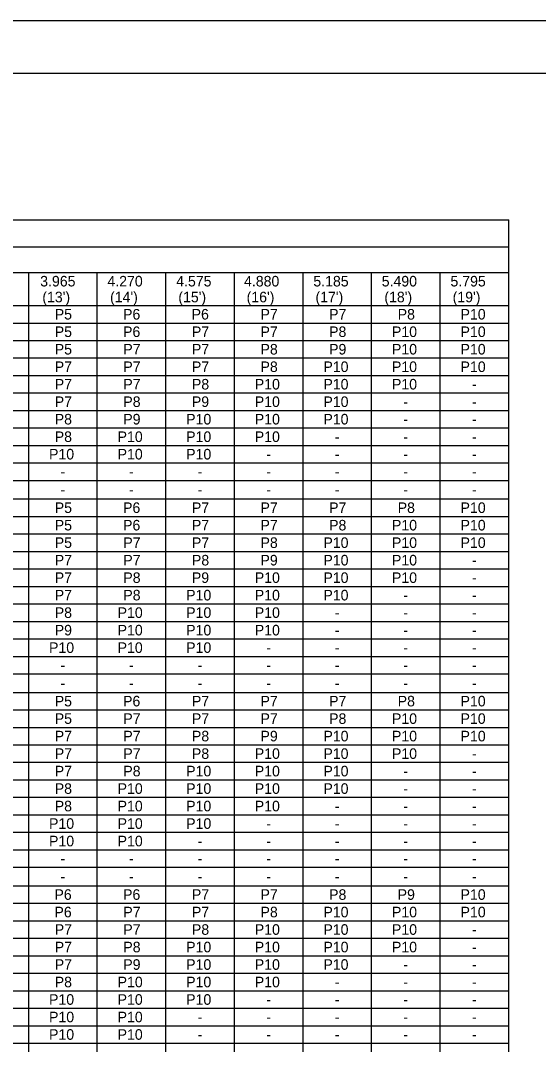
# Model space of a CAD drawing. Extents: x 637580 to 641008, y 294594 to 295782.
# Drawn here: x 639574.7 to 639722, y 295490.5 to 295781.6 of the extents above; entities that cross this region are included whole.
import ezdxf

# ---------------------------------------------------------------- set-up
doc = ezdxf.new("R2010")
doc.units = 0
for name, color, linetype in [('1', 7, 'Continuous'), ('2', 7, 'Continuous'), ('PLT-BNDY', 7, 'Continuous')]:
    doc.layers.add(name, color=color, linetype=linetype)

msp = doc.modelspace()

# ---------------------------------------------------------------- linework, layer by layer
at = {"layer": '1'}
for p, q in [((639302.31, 295766.63), (640088.31, 295766.63)), ((639346.67, 295724.98), (639713.6, 295724.98)), ((639713.6, 295260.68), (639713.6, 295724.98)), ((639346.67, 295717.3), (639713.6, 295717.3)), ((639346.67, 295700.6), (639713.6, 295700.6)), ((639346.67, 295645.61), (639713.6, 295645.61)), ((639346.67, 295590.62), (639713.6, 295590.62)), ((639346.67, 295535.63), (639713.6, 295535.63))]:
    msp.add_line(p, q, dxfattribs=at)
at = {"layer": '2'}
for p, q in [((639401.48, 295709.96), (639713.6, 295709.96)), ((639577.04, 295260.68), (639577.04, 295709.96)), ((639596.55, 295260.68), (639596.55, 295709.96)), ((639616.06, 295260.68), (639616.06, 295709.96)), ((639635.57, 295260.68), (639635.57, 295709.96)), ((639655.07, 295260.68), (639655.07, 295709.96)), ((639674.58, 295260.68), (639674.58, 295709.96)), ((639694.09, 295260.68), (639694.09, 295709.96)), ((639373.47, 295695.62), (639713.6, 295695.62)), ((639373.47, 295690.65), (639713.6, 295690.65)), ((639373.47, 295685.68), (639713.6, 295685.68)), ((639373.47, 295680.71), (639713.6, 295680.71)), ((639373.47, 295675.73), (639713.6, 295675.73)), ((639373.47, 295670.76), (639713.6, 295670.76)), ((639373.47, 295665.79), (639713.6, 295665.79)), ((639373.47, 295660.82), (639713.6, 295660.82)), ((639373.47, 295655.84), (639713.6, 295655.84)), ((639373.47, 295650.87), (639713.6, 295650.87)), ((639373.47, 295640.63), (639713.6, 295640.63)), ((639373.47, 295635.66), (639713.6, 295635.66)), ((639373.47, 295630.69), (639713.6, 295630.69)), ((639373.47, 295625.72), (639713.6, 295625.72)), ((639373.47, 295620.74), (639713.6, 295620.74)), ((639373.47, 295615.77), (639713.6, 295615.77)), ((639373.47, 295610.8), (639713.6, 295610.8)), ((639373.47, 295605.83), (639713.6, 295605.83)), ((639373.47, 295600.85), (639713.6, 295600.85)), ((639373.47, 295595.88), (639713.6, 295595.88)), ((639373.47, 295585.64), (639713.6, 295585.64)), ((639373.47, 295580.67), (639713.6, 295580.67)), ((639373.47, 295575.7), (639713.6, 295575.7)), ((639373.47, 295570.73), (639713.6, 295570.73)), ((639373.47, 295565.75), (639713.6, 295565.75)), ((639373.47, 295560.78), (639713.6, 295560.78)), ((639373.47, 295555.81), (639713.6, 295555.81)), ((639373.47, 295550.84), (639713.6, 295550.84)), ((639373.47, 295545.86), (639713.6, 295545.86)), ((639373.47, 295540.89), (639713.6, 295540.89)), ((639373.47, 295530.65), (639713.6, 295530.65)), ((639373.47, 295525.68), (639713.6, 295525.68)), ((639373.47, 295520.71), (639713.6, 295520.71)), ((639373.47, 295515.74), (639713.6, 295515.74)), ((639373.47, 295510.76), (639713.6, 295510.76)), ((639373.47, 295505.79), (639713.6, 295505.79)), ((639373.47, 295500.82), (639713.6, 295500.82)), ((639373.47, 295495.85), (639713.6, 295495.85)), ((639373.47, 295490.87), (639713.6, 295490.87))]:
    msp.add_line(p, q, dxfattribs=at)
at = {"layer": 'PLT-BNDY'}
msp.add_lwpolyline([(639262.31, 295781.63), (640103.31, 295781.63), (640103.31, 295187.63), (639262.31, 295187.63)], close=True, dxfattribs=at)

# ---------------------------------------------------------------- texts
at = {"layer": '1'}
for s, p in [('3.965', (639580.31, 295706.01)), ('4.270', (639599.43, 295706.01)), ('4.575', (639618.99, 295706.01)), ('4.880', (639638.28, 295706.01)), ('5.185', (639657.99, 295706.01)), ('5.490', (639677.44, 295706.01)), ('5.795', (639696.99, 295706.01)), ("(13')", (639580.92, 295701.51)), ("(14')", (639600.18, 295701.51)), ("(15')", (639619.6, 295701.51)), ("(16')", (639639.02, 295701.51)), ("(17')", (639658.6, 295701.51)), ("(18')", (639678.19, 295701.51)), ("(19')", (639697.61, 295701.51)), ('P5', (639584.45, 295696.61)), ('P6', (639603.87, 295696.61)), ('P6', (639623.38, 295696.61)), ('P7', (639642.97, 295696.61)), ('P7', (639662.48, 295696.61)), ('P8', (639681.98, 295696.61)), ('P10', (639699.86, 295696.61)), ('P5', (639584.45, 295691.64)), ('P6', (639603.87, 295691.64)), ('P7', (639623.46, 295691.64)), ('P7', (639642.97, 295691.64)), ('P8', (639662.48, 295691.64)), ('P10', (639680.35, 295691.64)), ('P10', (639699.86, 295691.64)), ('P5', (639584.45, 295686.67)), ('P7', (639603.95, 295686.67)), ('P7', (639623.46, 295686.67)), ('P8', (639642.97, 295686.67)), ('P9', (639662.47, 295686.67)), ('P10', (639680.35, 295686.67)), ('P10', (639699.86, 295686.67)), ('P7', (639584.45, 295681.69)), ('P7', (639603.95, 295681.69)), ('P7', (639623.46, 295681.69)), ('P8', (639642.97, 295681.69)), ('P10', (639660.85, 295681.69)), ('P10', (639680.35, 295681.69)), ('P10', (639699.86, 295681.69)), ('P7', (639584.45, 295676.72)), ('P7', (639603.95, 295676.72)), ('P8', (639623.46, 295676.72)), ('P10', (639641.34, 295676.72)), ('P10', (639660.85, 295676.72)), ('P10', (639680.35, 295676.72)), ('-', (639703.11, 295676.72)), ('P7', (639584.45, 295671.75)), ('P8', (639603.95, 295671.75)), ('P9', (639623.45, 295671.75)), ('P10', (639641.34, 295671.75)), ('P10', (639660.85, 295671.75)), ('-', (639683.6, 295671.75)), ('-', (639703.11, 295671.75)), ('P8', (639584.45, 295666.78)), ('P9', (639603.94, 295666.78)), ('P10', (639621.83, 295666.78)), ('P10', (639641.34, 295666.78)), ('P10', (639660.85, 295666.78)), ('-', (639683.6, 295666.78)), ('-', (639703.11, 295666.78)), ('P8', (639584.45, 295661.8)), ('P10', (639602.33, 295661.8)), ('P10', (639621.83, 295661.8)), ('P10', (639641.34, 295661.8)), ('-', (639664.1, 295661.8)), ('-', (639683.6, 295661.8)), ('-', (639703.11, 295661.8)), ('P10', (639582.82, 295656.83)), ('P10', (639602.33, 295656.83)), ('P10', (639621.83, 295656.83)), ('-', (639644.59, 295656.83)), ('-', (639664.1, 295656.83)), ('-', (639683.6, 295656.83)), ('-', (639703.11, 295656.83)), ('-', (639586.07, 295651.86)), ('-', (639605.57, 295651.86)), ('-', (639625.08, 295651.86)), ('-', (639644.59, 295651.86)), ('-', (639664.1, 295651.86)), ('-', (639683.6, 295651.86)), ('-', (639703.11, 295651.86)), ('-', (639586.07, 295646.74)), ('-', (639605.57, 295646.74)), ('-', (639625.08, 295646.74)), ('-', (639644.59, 295646.74)), ('-', (639664.1, 295646.74)), ('-', (639683.6, 295646.74)), ('-', (639703.11, 295646.74)), ('P5', (639584.45, 295641.62)), ('P6', (639603.87, 295641.62)), ('P7', (639623.46, 295641.62)), ('P7', (639642.97, 295641.62)), ('P7', (639662.48, 295641.62)), ('P8', (639681.98, 295641.62)), ('P10', (639699.86, 295641.62)), ('P5', (639584.45, 295636.65)), ('P6', (639603.87, 295636.65)), ('P7', (639623.46, 295636.65)), ('P7', (639642.97, 295636.65)), ('P8', (639662.48, 295636.65)), ('P10', (639680.35, 295636.65)), ('P10', (639699.86, 295636.65)), ('P5', (639584.45, 295631.68)), ('P7', (639603.95, 295631.68)), ('P7', (639623.46, 295631.68)), ('P8', (639642.97, 295631.68)), ('P10', (639660.85, 295631.68)), ('P10', (639680.35, 295631.68)), ('P10', (639699.86, 295631.68)), ('P7', (639584.45, 295626.7)), ('P7', (639603.95, 295626.7)), ('P8', (639623.46, 295626.7)), ('P9', (639642.96, 295626.7)), ('P10', (639660.85, 295626.7)), ('P10', (639680.35, 295626.7)), ('-', (639703.11, 295626.7)), ('P7', (639584.45, 295621.73)), ('P8', (639603.95, 295621.73)), ('P9', (639623.45, 295621.73)), ('P10', (639641.34, 295621.73)), ('P10', (639660.85, 295621.73)), ('P10', (639680.35, 295621.73)), ('-', (639703.11, 295621.73)), ('P7', (639584.45, 295616.76)), ('P8', (639603.95, 295616.76)), ('P10', (639621.83, 295616.76)), ('P10', (639641.34, 295616.76)), ('P10', (639660.85, 295616.76)), ('-', (639683.6, 295616.76)), ('-', (639703.11, 295616.76)), ('P8', (639584.45, 295611.79)), ('P10', (639602.33, 295611.79)), ('P10', (639621.83, 295611.79)), ('P10', (639641.34, 295611.79)), ('-', (639664.1, 295611.79)), ('-', (639683.6, 295611.79)), ('-', (639703.11, 295611.79)), ('P9', (639584.44, 295606.81)), ('P10', (639602.33, 295606.81)), ('P10', (639621.83, 295606.81)), ('P10', (639641.34, 295606.81)), ('-', (639664.1, 295606.81)), ('-', (639683.6, 295606.81)), ('-', (639703.11, 295606.81)), ('P10', (639582.82, 295601.84)), ('P10', (639602.33, 295601.84)), ('P10', (639621.83, 295601.84)), ('-', (639644.59, 295601.84)), ('-', (639664.1, 295601.84)), ('-', (639683.6, 295601.84)), ('-', (639703.11, 295601.84)), ('-', (639586.07, 295596.87)), ('-', (639605.57, 295596.87)), ('-', (639625.08, 295596.87)), ('-', (639644.59, 295596.87)), ('-', (639664.1, 295596.87)), ('-', (639683.6, 295596.87)), ('-', (639703.11, 295596.87)), ('-', (639586.07, 295591.75)), ('-', (639605.57, 295591.75)), ('-', (639625.08, 295591.75)), ('-', (639644.59, 295591.75)), ('-', (639664.1, 295591.75)), ('-', (639683.6, 295591.75)), ('-', (639703.11, 295591.75)), ('P5', (639584.45, 295586.63)), ('P6', (639603.87, 295586.63)), ('P7', (639623.46, 295586.63)), ('P7', (639642.97, 295586.63)), ('P7', (639662.48, 295586.63)), ('P8', (639681.98, 295586.63)), ('P10', (639699.86, 295586.63)), ('P5', (639584.45, 295581.66)), ('P7', (639603.95, 295581.66)), ('P7', (639623.46, 295581.66)), ('P7', (639642.97, 295581.66)), ('P8', (639662.48, 295581.66)), ('P10', (639680.35, 295581.66)), ('P10', (639699.86, 295581.66)), ('P7', (639584.45, 295576.69)), ('P7', (639603.95, 295576.69)), ('P8', (639623.46, 295576.69)), ('P9', (639642.96, 295576.69)), ('P10', (639660.85, 295576.69)), ('P10', (639680.35, 295576.69)), ('P10', (639699.86, 295576.69)), ('P7', (639584.45, 295571.71)), ('P7', (639603.95, 295571.71)), ('P8', (639623.46, 295571.71)), ('P10', (639641.34, 295571.71)), ('P10', (639660.85, 295571.71)), ('P10', (639680.35, 295571.71)), ('-', (639703.11, 295571.71)), ('P7', (639584.45, 295566.74)), ('P8', (639603.95, 295566.74)), ('P10', (639621.83, 295566.74)), ('P10', (639641.34, 295566.74)), ('P10', (639660.85, 295566.74)), ('-', (639683.6, 295566.74)), ('-', (639703.11, 295566.74)), ('P8', (639584.45, 295561.77)), ('P10', (639602.33, 295561.77)), ('P10', (639621.83, 295561.77)), ('P10', (639641.34, 295561.77)), ('P10', (639660.85, 295561.77)), ('-', (639683.6, 295561.77)), ('-', (639703.11, 295561.77)), ('P8', (639584.45, 295556.8)), ('P10', (639602.33, 295556.8)), ('P10', (639621.83, 295556.8)), ('P10', (639641.34, 295556.8)), ('-', (639664.1, 295556.8)), ('-', (639683.6, 295556.8)), ('-', (639703.11, 295556.8)), ('P10', (639582.82, 295551.82)), ('P10', (639602.33, 295551.82)), ('P10', (639621.83, 295551.82)), ('-', (639644.59, 295551.82)), ('-', (639664.1, 295551.82)), ('-', (639683.6, 295551.82)), ('-', (639703.11, 295551.82)), ('P10', (639582.82, 295546.85)), ('P10', (639602.33, 295546.85)), ('-', (639625.08, 295546.85)), ('-', (639644.59, 295546.85)), ('-', (639664.1, 295546.85)), ('-', (639683.6, 295546.85)), ('-', (639703.11, 295546.85)), ('-', (639586.07, 295541.88)), ('-', (639605.57, 295541.88)), ('-', (639625.08, 295541.88)), ('-', (639644.59, 295541.88)), ('-', (639664.1, 295541.88)), ('-', (639683.6, 295541.88)), ('-', (639703.11, 295541.88)), ('-', (639586.07, 295536.76)), ('-', (639605.57, 295536.76)), ('-', (639625.08, 295536.76)), ('-', (639644.59, 295536.76)), ('-', (639664.1, 295536.76)), ('-', (639683.6, 295536.76)), ('-', (639703.11, 295536.76)), ('P6', (639584.36, 295531.64)), ('P6', (639603.87, 295531.64)), ('P7', (639623.46, 295531.64)), ('P7', (639642.97, 295531.64)), ('P8', (639662.48, 295531.64)), ('P9', (639681.97, 295531.64)), ('P10', (639699.86, 295531.64)), ('P6', (639584.36, 295526.67)), ('P7', (639603.95, 295526.67)), ('P7', (639623.46, 295526.67)), ('P8', (639642.97, 295526.67)), ('P10', (639660.85, 295526.67)), ('P10', (639680.35, 295526.67)), ('P10', (639699.86, 295526.67)), ('P7', (639584.45, 295521.7)), ('P7', (639603.95, 295521.7)), ('P8', (639623.46, 295521.7)), ('P10', (639641.34, 295521.7)), ('P10', (639660.85, 295521.7)), ('P10', (639680.35, 295521.7)), ('-', (639703.11, 295521.7)), ('P7', (639584.45, 295516.72)), ('P8', (639603.95, 295516.72)), ('P10', (639621.83, 295516.72)), ('P10', (639641.34, 295516.72)), ('P10', (639660.85, 295516.72)), ('P10', (639680.35, 295516.72)), ('-', (639703.11, 295516.72)), ('P7', (639584.45, 295511.75)), ('P9', (639603.94, 295511.75)), ('P10', (639621.83, 295511.75)), ('P10', (639641.34, 295511.75)), ('P10', (639660.85, 295511.75)), ('-', (639683.6, 295511.75)), ('-', (639703.11, 295511.75)), ('P8', (639584.45, 295506.78)), ('P10', (639602.33, 295506.78)), ('P10', (639621.83, 295506.78)), ('P10', (639641.34, 295506.78)), ('-', (639664.1, 295506.78)), ('-', (639683.6, 295506.78)), ('-', (639703.11, 295506.78)), ('P10', (639582.82, 295501.81)), ('P10', (639602.33, 295501.81)), ('P10', (639621.83, 295501.81)), ('-', (639644.59, 295501.81)), ('-', (639664.1, 295501.81)), ('-', (639683.6, 295501.81)), ('-', (639703.11, 295501.81)), ('P10', (639582.82, 295496.83)), ('P10', (639602.33, 295496.83)), ('-', (639625.08, 295496.83)), ('-', (639644.59, 295496.83)), ('-', (639664.1, 295496.83)), ('-', (639683.6, 295496.83)), ('-', (639703.11, 295496.83)), ('P10', (639582.82, 295491.86)), ('P10', (639602.33, 295491.86)), ('-', (639625.08, 295491.86)), ('-', (639644.59, 295491.86)), ('-', (639664.1, 295491.86)), ('-', (639683.6, 295491.86)), ('-', (639703.11, 295491.86))]:
    msp.add_text(s, height=3, dxfattribs=at).set_placement(p)

doc.saveas('drawing.dxf')
